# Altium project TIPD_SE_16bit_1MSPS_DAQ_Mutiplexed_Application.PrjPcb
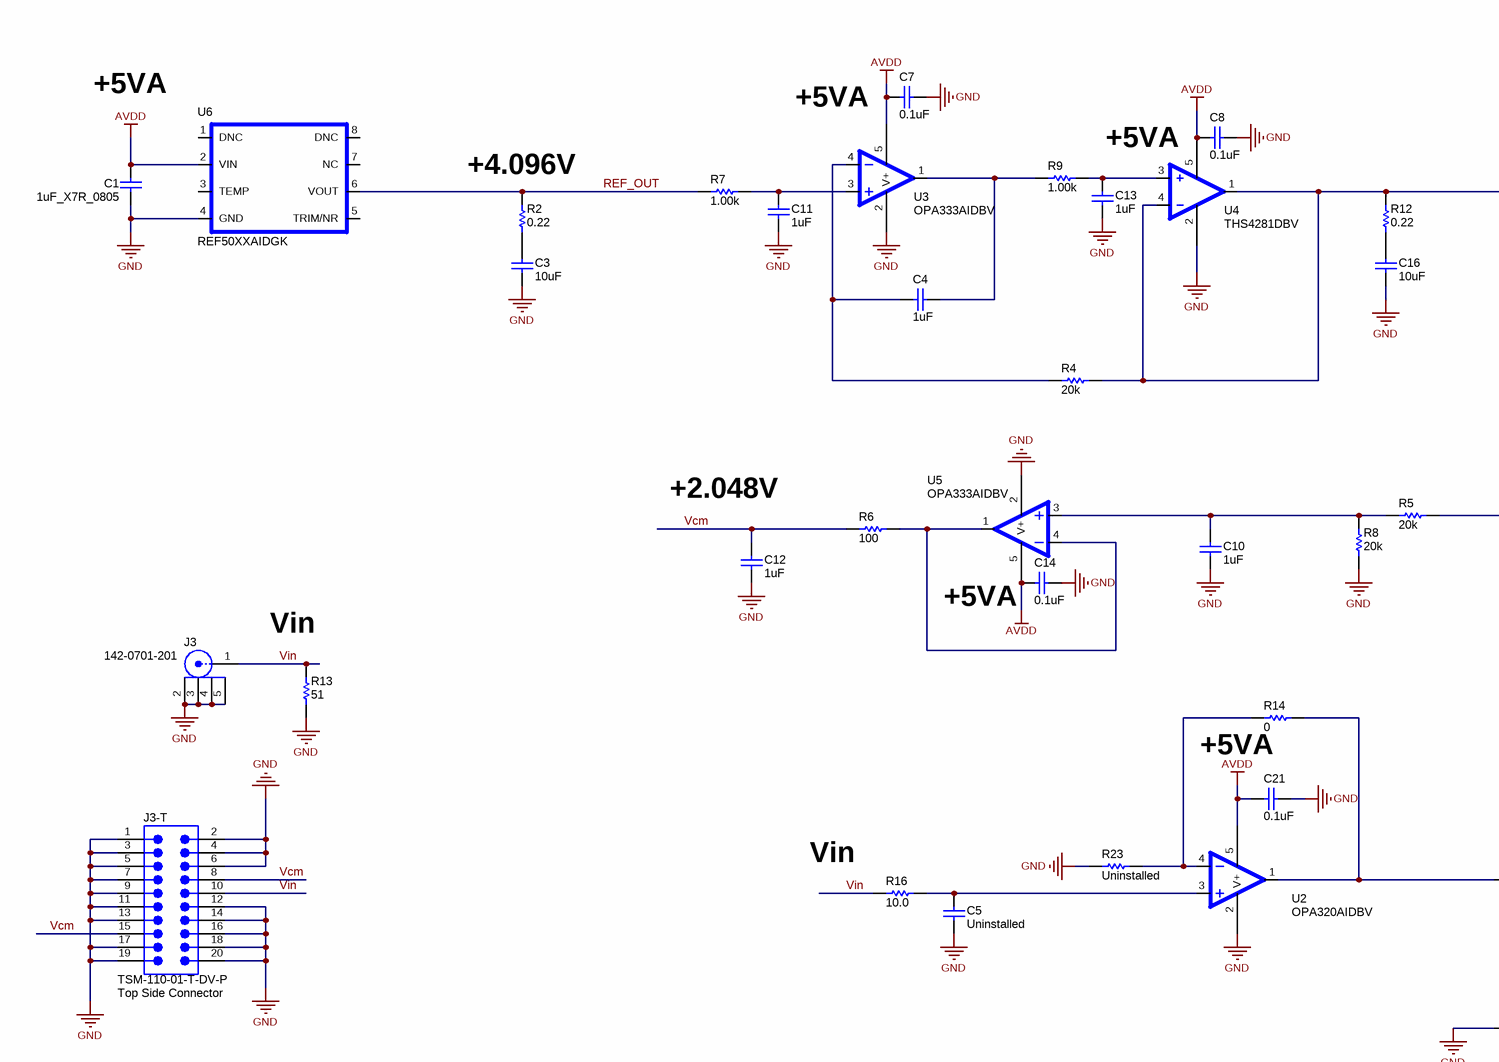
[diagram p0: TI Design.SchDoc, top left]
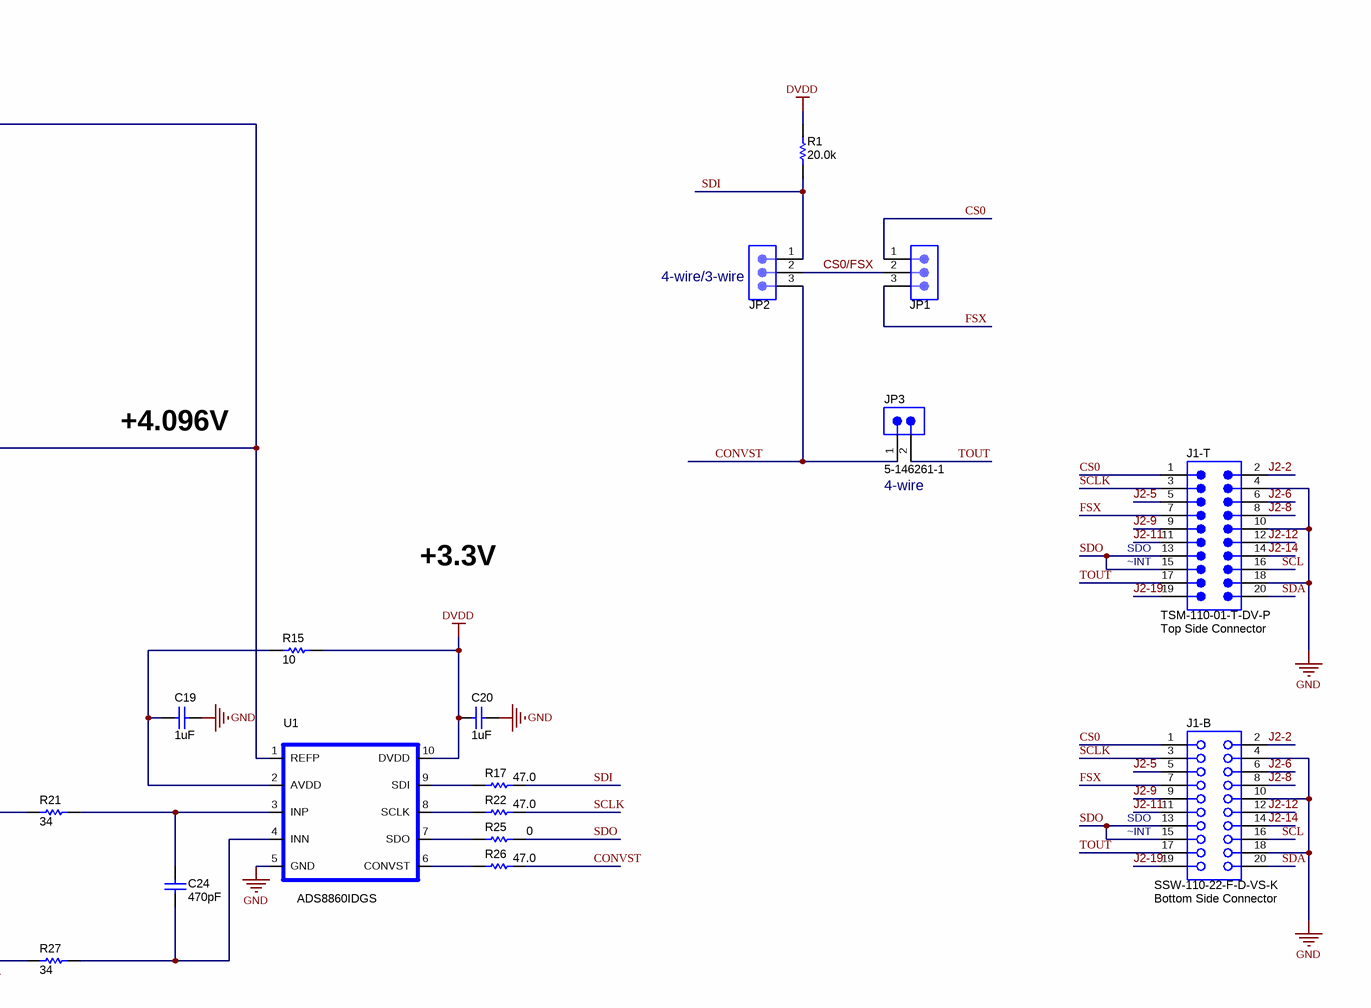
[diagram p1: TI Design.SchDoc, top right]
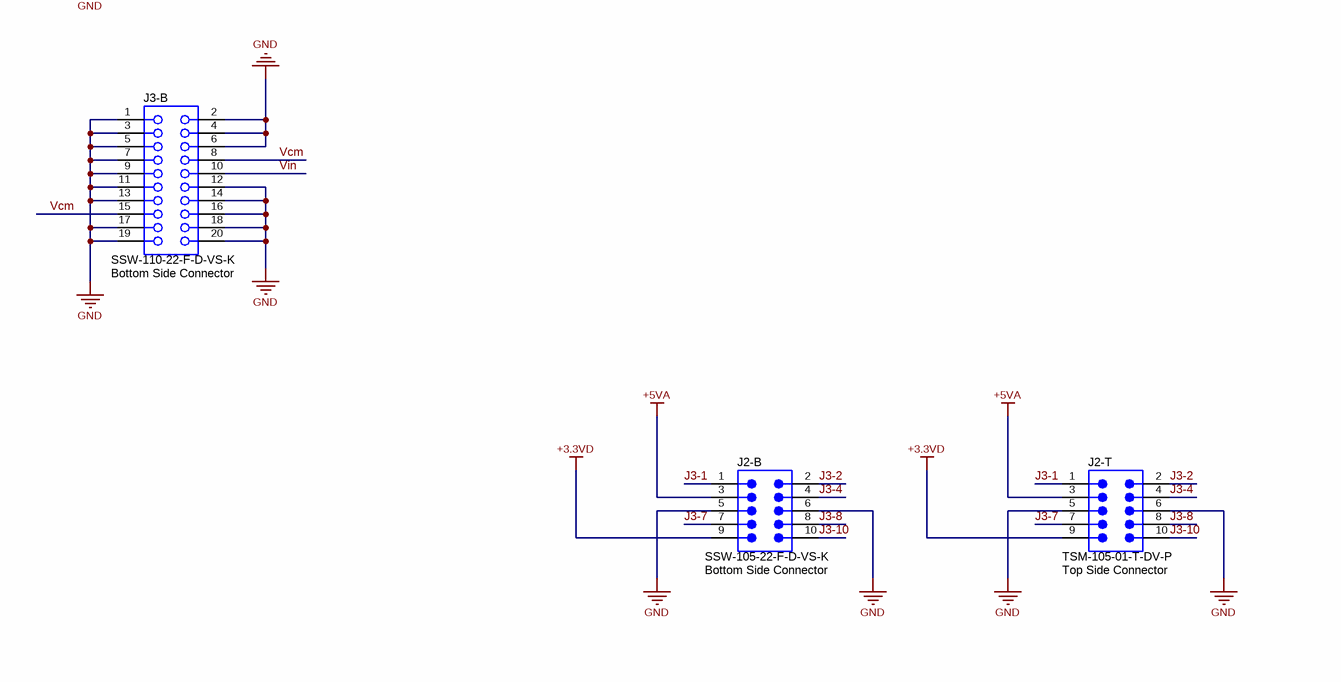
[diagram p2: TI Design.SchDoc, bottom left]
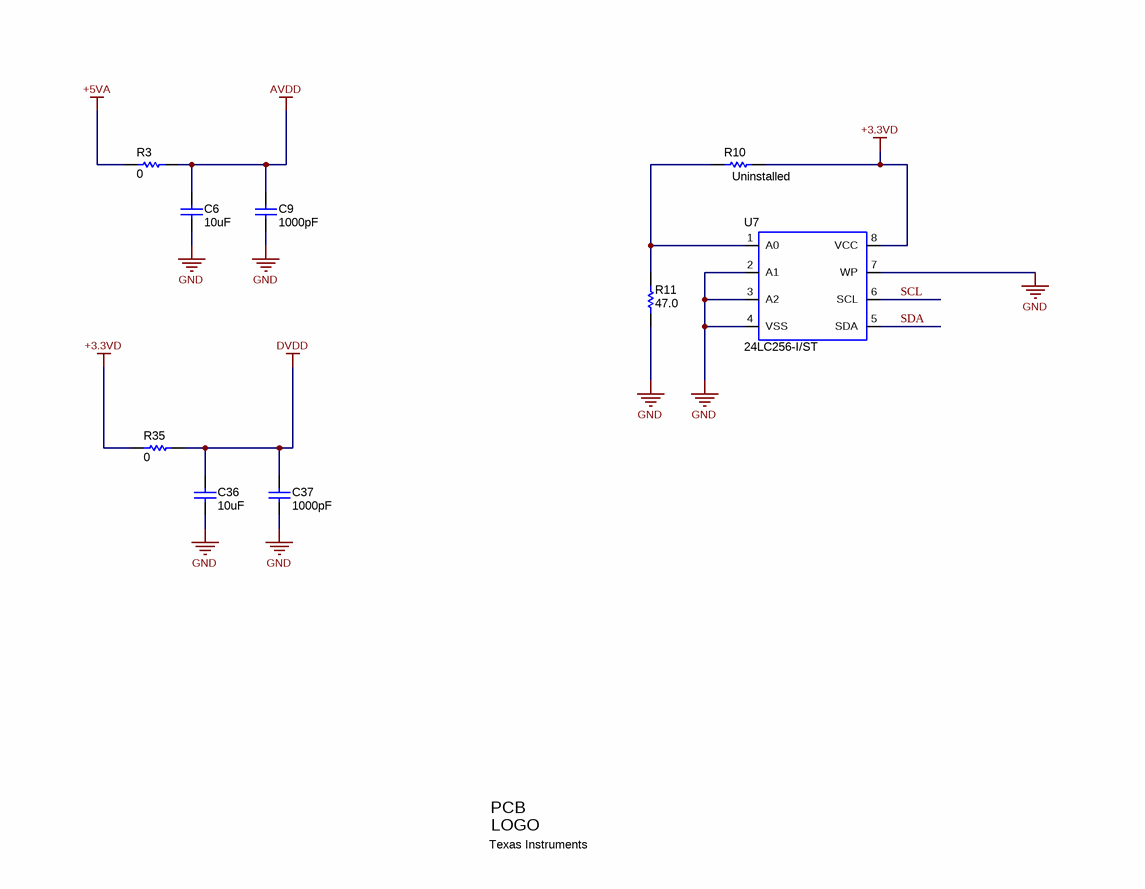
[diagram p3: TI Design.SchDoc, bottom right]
TechSupport: http://www.e2e.ti.com; SCH_Rev: Rev A; PRJ_Title: Schematic for TIDU504; PRJ_Number: TIPD173; PRJ_Engineer: Jason Wu; PRJ_Customer: Precision Converter; PCB_Rev: Rev A; PCB_Layout: Jason Wu; CopyrightYear: 2014
1 sheet, 62 parts. Net scope: global (net labels, ports and power ports of the same name join across sheets).
Board file: TI Design.PcbDoc

## Sheet TI Design.SchDoc: Schematic for TIDU504
size 558 x 431 mm; Date: Not shown in title block; ApprovedBy: Not shown in title block; CheckedBy: Not shown in title block; Author: Not shown in title block; CompanyName: Not shown in title block; Engineer: Not shown in title block; Organization: Not shown in title block; Address1: Not shown in title block; Address2: Not shown in title block; Address3: Not shown in title block; Address4: Not shown in title block; DocumentNumber: 1; Revision: Use project parameter SCH_Rev; SheetNumber: 1; SheetTotal: 1; PageSetup: Record=PageOptions|CenterHorizontal=True|CenterVertical=True|PrintScale=0.62|XCorrection=1.00|YCorrection=1.00|PrintKind=0|BorderSize=5000000|LeftOffset=0|BottomOffset=0|Orientation=2|PaperLength=1000|PaperWidth=1000|Scale=100|PaperSource=15|PrintQuality=600|MediaType=1|DitherType=10|PaperKind=Tabloid (11 x 17")|PrintScaleMode=1

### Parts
C1  ValueDisplayed: 1uF_X7R_0805  [0805_HV]  (hidden comment: C0805C105K8RACTU)
C3  ValueDisplayed: 10uF  [0805_HV]  (hidden comment: GRM21BR70J106KE76L)
C4  ValueDisplayed: 1uF  [0603]  (hidden comment: GRM188R70J105KA01D)
C5  ValueDisplayed: Uninstalled  [0603]  (hidden comment: GRM1885C1E102JA01D)
C6  ValueDisplayed: 10uF  [0805_HV]  (hidden comment: GRM21BR61E106MA73)
C7  ValueDisplayed: 0.1uF  [0603]  (hidden comment: 0603YC104JAT2A)
C8  ValueDisplayed: 0.1uF  [0603]  (hidden comment: 0603YC104JAT2A)
C9  ValueDisplayed: 1000pF  [0603]  (hidden comment: C0603C102J5GAC)
C10  ValueDisplayed: 1uF  [0603]  (hidden comment: GRM188R70J105KA01D)
C11  ValueDisplayed: 1uF  [0603]  (hidden comment: GRM188R70J105KA01D)
C12  ValueDisplayed: 1uF  [0603]  (hidden comment: GRM188R70J105KA01D)
C13  ValueDisplayed: 1uF  [0603]  (hidden comment: GRM188R70J105KA01D)
C14  ValueDisplayed: 0.1uF  [0603]  (hidden comment: 0603YC104JAT2A)
C16  ValueDisplayed: 10uF  [0805_HV]  (hidden comment: GRM21BR71A106KE51L)
C19  ValueDisplayed: 1uF  [0603]  (hidden comment: GRM188R71E105KA12D)
C20  ValueDisplayed: 1uF  [0603]  (hidden comment: GRM188R71E105KA12D)
C21  ValueDisplayed: 0.1uF  [0603]  (hidden comment: 0603YC104JAT2A)
C24  ValueDisplayed: 470pF  [0603]  (hidden comment: GRM1885C1E102JA01D)
C36  ValueDisplayed: 10uF  [0805_HV]  (hidden comment: GRM21BR61E106MA73)
C37  ValueDisplayed: 1000pF  [0603]  (hidden comment: C0603C102J5GAC)
J1-B  Bottom Side Connector  [CONN_SSW-110-22-F-D-VS-K]
J1-T  TSM-110-01-T-DV-P  Comment_1: Top Side Connector  [CONN_TSM-110-01-T-DV-P]
J2-B  SSW-105-22-F-D-VS-K  Comment_1: Bottom Side Connector  [CONN_SSW-105-22-F-D-VS-K]
J2-T  TSM-105-01-T-DV-P  Comment_1: Top Side Connector  [CONN_TSM-105-01-T-DV-P]
J3  142-0701-201  [Johnson_142-0701-20x]
J3-B  Bottom Side Connector  [CONN_SSW-110-22-F-D-VS-K]
J3-T  TSM-110-01-T-DV-P  Comment_1: Top Side Connector  [CONN_TSM-110-01-T-DV-P]
JP1  PBC03SAAN  [PBC03SAAN]  (value not drawn)
JP2  PBC03SAAN  [PBC03SAAN]  (value not drawn)
JP3  5-146261-1  [CONN_5-146261-1]
Logo1  Texas Instruments  [TI_Stacked_SolderMask_Medium]  (no BOM)
R1  value 20.0k  [0603]  (hidden comment: CRCW060320K0FKEA)
R2  value 0.22  [0603]  (hidden comment: CRCW060320K0FKEA)
R3  value 0  [0603]  (hidden comment: ERJ-3GEY0R00V)
R4  value 20k  [0603]  (hidden comment: CRCW060320K0FKEA)
R5  value 20k  [0603]  (hidden comment: RG1608P-102-B-T5)
R6  value 100  [0603]  (hidden comment: RG1608P-102-B-T5)
R7  value 1.00k  [0603]  (hidden comment: RG1608P-102-B-T5)
R8  value 20k  [0603]  (hidden comment: RG1608P-102-B-T5)
R9  value 1.00k  [0603]  (hidden comment: RG1608P-102-B-T5)
R10  Uninstalled  [0603]
R11  value 47.0  [0603]  (hidden comment: RC0603FR-0747RL)
R12  value 0.22  [0603]  (hidden comment: ERJ-3RQFR22V)
R13  value 51  [0805_HV]  (hidden comment: RG2012P-510-B-T5)
R14  value 0  [0603]  (hidden comment: RC0603FR-0710RL)
R15  value 10  [0603]  (hidden comment: RC0603FR-0710RL)
R16  value 10.0  [0603]  (hidden comment: RC0603FR-0710RL)
R17  value 47.0  [0603]  (hidden comment: RC0603FR-0710RL)
R21  value 34  [0603]  (hidden comment: RC0603FR-0710RL)
R22  value 47.0  [0603]  (hidden comment: RC0603FR-0710RL)
R23  value Uninstalled  [0603]  (hidden comment: RC0603FR-0710RL)
R25  value 0  [0603]  (hidden comment: RC0603FR-0710RL)
R26  value 47.0  [0603]  (hidden comment: RC0603FR-0710RL)
R27  value 34  [0603]  (hidden comment: RC0603FR-0710RL)
R35  value 0  [0603]  (hidden comment: ERJ-3GEY0R00V)
U1  ADS8860IDGS  [DGS_10P2]
U2  OPA320AIDBV  [SOT23-5P]
U3  OPA333AIDBV  [SOT23-5P]
U4  THS4281DBV  [DBV-5]
U5  OPA333AIDBV  [SOT23-5P]
U6  REF50XXAIDGK  [DGK8]
U7  24LC256-I/ST  [TSSOP-8]

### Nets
+3.3VD: J2-B.9 J2-T.9 R10.2 R35.1 U7.8(VCC)
+5VA: J2-B.3 J2-T.3 R3.1
AVDD: C1.1 C6.1 C7.1 C8.1 C9.2 C14.1 C21.1 R3.2 U2.5(V+) U3.5(V+) U4.5(VDD) U5.5(V+) U6.2(VIN)
DVDD: C20.2 C36.1 C37.2 R1.1 R15.2 R35.2 U1.10(DVDD)
GND: C1.2 C3.2 C5.2 C6.2 C7.2 C8.2 C9.1 C10.1 C11.1 C12.1 C13.1 C14.2 C16.1 C19.1 C20.1 C21.2 C36.2 C37.1 J1-B.4 J1-B.10 J1-B.18 J1-T.4 J1-T.10 J1-T.18 J2-B.5 J2-B.6 J2-T.5 J2-T.6 J3.2 J3.3 J3.4 J3.5 J3-B.1 J3-B.2 J3-B.3 J3-B.4 J3-B.5 J3-B.6 J3-B.7 J3-B.9 J3-B.11 J3-B.12 J3-B.13 J3-B.14 J3-B.16 J3-B.17 J3-B.18 J3-B.19 J3-B.20 J3-T.1 J3-T.2 J3-T.3 J3-T.4 J3-T.5 J3-T.6 J3-T.7 J3-T.9 J3-T.11 J3-T.12 J3-T.13 J3-T.14 J3-T.16 J3-T.17 J3-T.18 J3-T.19 J3-T.20 R8.1 R11.2 R13.1 R23.1 R27.1 U1.5(GND) U2.2(V-) U3.2(V-) U4.2(GND) U5.2(V-) U6.4(GND) U7.2(A1) U7.3(A2) U7.4(VSS) U7.7(WP)
CONVST: JP2.3 JP3.1 R26.2
CS0: J1-B.1 J1-T.1 JP1.1
CS0/FSX: JP1.2 JP2.2
FSX: J1-B.7 J1-T.7 JP1.3
J2-2: J1-B.2 J1-T.2
J2-5: J1-B.5 J1-T.5
J2-6: J1-B.6 J1-T.6
J2-8: J1-B.8 J1-T.8
J2-9: J1-B.9 J1-T.9
J2-11: J1-B.11 J1-T.11
J2-12: J1-B.12 J1-T.12
J2-14: J1-B.14 J1-T.14
J2-19: J1-B.19 J1-T.19
J3-1: J2-B.1 J2-T.1
J3-2: J2-B.2 J2-T.2
J3-4: J2-B.4 J2-T.4
J3-7: J2-B.7 J2-T.7
J3-8: J2-B.8 J2-T.8
J3-10: J2-B.10 J2-T.10
REF_OUT: R2.1 R7.1 U6.6(VOUT)
SCL: J1-B.16 J1-T.16 U7.6(SCL)
SCLK: J1-B.3 J1-T.3 R22.2
SDA: J1-B.20 J1-T.20 U7.5(SDA)
SDI: JP2.1 R1.2 R17.2
SDO: J1-B.13 J1-B.15 J1-T.13 J1-T.15 R25.2
TOUT: J1-B.17 J1-T.17 JP3.2
Vcm: C12.2 J3-B.8 J3-B.15 J3-T.8 J3-T.15 R6.1
Vin: J3.1 J3-B.10 J3-T.10 R13.2 R16.1
NetC3_1: C3.1 R2.2
NetC4_1: C4.1 R9.1 U3.1(OUT)
NetC4_2: C4.2 R4.2 U3.4
NetC5_1: C5.1 R16.2 U2.3
NetC10_2: C10.2 R5.1 R8.2 U5.3
NetC11_2: C11.2 R7.2 U3.3
NetC13_2: C13.2 R9.2 U4.3
NetC16_2: C16.2 R12.1
NetC19_2: C19.2 R15.1 U1.2(AVDD)
NetC24_1: C24.1 R21.2 U1.3(INP)
NetC24_2: C24.2 R27.2 U1.4(INN)
NetR4_1: R4.1 R5.2 R12.2 U1.1(REFP) U4.1(OUT) U4.4
NetR6_2: R6.2 U5.1(OUT) U5.4
NetR10_1: R10.1 R11.1 U7.1(A0)
NetR14_1: R14.1 R23.2 U2.4
NetR14_2: R14.2 R21.1 U2.1(OUT)
NetR17_1: R17.1 U1.9(SDI)
NetR22_1: R22.1 U1.8(SCLK)
NetR25_1: R25.1 U1.7(SDO)
NetR26_1: R26.1 U1.6(CONVST)

Not connected (* = marked no-connect by the designer): U6 1(DNC) 3(TEMP) 5(TRIM/NR) 7(NC) 8(DNC)

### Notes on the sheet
- +5VA
- (near R2) +4.096V
- (near JP2) 4-wire/3-wire
- (near C12) +2.048V
- +4.096V
- (near JP3) 4-wire
- Vin
- +3.3V
- (near J1-T) SDO
- (near J1-T) ~INT
- (near R14) +5VA
- (near R16) Vin
- (near J1-B) SDO
- (near J1-B) ~INT

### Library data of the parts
C1 = C0805C105K8RACTU: CAP, CERM, 1uF, 10V, +/-10%, X7R, 0805; Manufacturer: Kemet; Polarized: N; CompType: Capacitor; U/M: EA; Cap_F: 0.000001; Tolerance_%: 10; ESR_Ohm: 0.015; Value1: 0.015 ohm; IRMS_A: 8.19; TaMin_C: -55; TaMax_C: 125; Cap_Case: 0805
C3 = GRM21BR70J106KE76L: CAP, CERM, 10uF, 6.3V, +/-10%, X7R, 0805; Manufacturer: MuRata; Polarized: N; CompType: Capacitor; U/M: EA; Cap_F: 0.00001; Tolerance_%: 10; Value1: Unknown; VDC_V: 6.3; TaMin_C: -55; TaMax_C: 125; Cap_Case: 0805
C4 C10-C13 = GRM188R70J105KA01D: CAP, CERM, 1uF, 6.3V, +/-10%, X7R, 0603; Manufacturer: MuRata; Polarized: N; CompType: Capacitor; U/M: EA; Cap_F: 0.000001; Tolerance_%: 10; VDC_V: 6.3; TaMin_C: -55; TaMax_C: 125
C5 C24 = GRM1885C1E102JA01D: CAP, CERM, 1000pF, 25V, +/-5%, C0G/NP0, 0603; Manufacturer: MuRata; Polarized: N; CompType: Capacitor; U/M: EA; Cap_F: 0.000000001; Tolerance_%: 5; Value1: Unknown; VDC_V: 25; TaMin_C: -55; TaMax_C: 125
C6 C36 = GRM21BR61E106MA73: CAP, CERM, 10uF, 25V, +/-20%, X5R, 0805; Manufacturer: MuRata; Polarized: N; CompType: Capacitor; U/M: EA; Cap_F: 0.00001; Tolerance_%: 20; Value1: Unknown; VDC_V: 25; TaMin_C: -55; TaMax_C: 85; Cap_Case: 0805
C7 C8 C14 C21 = 0603YC104JAT2A: CAP, CERM, 0.1uF, 16V, +/-5%, X7R, 0603; Manufacturer: AVX; Polarized: N; CompType: Capacitor; U/M: EA; Cap_F: 0.0000001; Tolerance_%: 5; ESR_Ohm: 0.039; Value1: 0.039 ohm; VDC_V: 16; TaMin_C: -55; TaMax_C: 125
C9 C37 = C0603C102J5GAC: CAP, CERM, 1000pF, 50V, +/-5%, C0G/NP0, 0603; Manufacturer: Kemet; Polarized: N; CompType: Capacitor; U/M: EA; Cap_F: 0.000000001; Tolerance_%: 5; Value1: Unknown; VDC_V: 50; TaMin_C: -55; TaMax_C: 125
C16 = GRM21BR71A106KE51L: CAP, CERM, 10uF, 10V, +/-10%, X7R, 0805; Manufacturer: MuRata; Polarized: N; CompType: Capacitor; U/M: EA; Cap_F: 0.00001; Tolerance_%: 10; ESR_Ohm: 0.003; Value1: 0.003 ohm; TaMin_C: -55; TaMax_C: 125; Cap_Case: 0805
C19 C20 = GRM188R71E105KA12D: CAP, CERM, 1uF, 25V, +/-10%, X7R, 0603; Manufacturer: MuRata; Polarized: N; CompType: Capacitor; U/M: EA; Cap_F: 0.000001; Tolerance_%: 10; Value1: Unknown; VDC_V: 25; TaMin_C: -55; TaMax_C: 125
J1-B J3-B = SSW-110-22-F-D-VS-K: Connector, Receptacle, 100mil, 10x2, Gold plated, SMD; Manufacturer: Samtec, Inc.; SymbolCreator: a0412235; U/M: EA
J1-T J3-T = TSM-110-01-T-DV-P: Header, 100mil, 10x2, SMD; Manufacturer: Samtec, Inc.; SymbolCreator: a0412235; CompType: Connector; U/M: EA
J2-B = SSW-105-22-F-D-VS-K: Connector, Header, 10-Pos (10x2), Receptacle, 100x100-mil Pitch; Manufacturer: Samtec, Inc.; SymbolCreator: a0412235; U/M: EA
J2-T = TSM-105-01-T-DV-P: Header, 100mil, 5x2, SMD; Manufacturer: Samtec, Inc.; SymbolCreator: a0412235; CompType: Connector; U/M: EA
J3 = 142-0701-201: Connector, TH, SMA; Manufacturer: Emerson Network Power; SymbolCreator: X0208326; U/M: EA
JP1 JP2 = PBC03SAAN: Header, TH, 100mil, 1x3, Gold plated, 230 mil above insulator; Manufacturer: Sullins Connector Solutions; U/M: EA
JP3 = 5-146261-1: Header, 100mil, 2x1, Gold plated, TH; Manufacturer: TE Connectivity; SymbolCreator: a0412235; U/M: EA
Logo1 = TI_Logo: Texas Instrument Corporate Signature; SymbolCreator: a0412235
R1 = CRCW060320K0FKEA: RES, 20.0k ohm, 1%, 0.1W, 0603; Manufacturer: Vishay-Dale; CompType: Resistor; Res_ohm: 20000; Value_Code: 20k0; Tolerance_%: 1; Power_W: 0.1; VDC_V: 75; TempCo: 100 ppm/C; EIA_Code: E96; U/M: EA
R2 R4 = CRCW060320K0FKEA: RES, 20.0k ohm, 1%, 0.1W, 0603; Manufacturer: Vishay-Dale; Alternate Manufacturer: Any; Alternate PartNumber: Equivalent; CompType: Resistor; Res_ohm: 20000; Value_Code: 20k0; Tolerance_%: 1; Power_W: 0.1; VDC_V: 75; TempCo: 100 ppm/C; EIA_Code: E96; U/M: EA
R3 R35 = ERJ-3GEY0R00V: RES, 0 ohm, 5%, 0.1W, 0603; Manufacturer: Panasonic; CompType: Resistor; Value_Code: 0000; Tolerance_%: 5; Power_W: 0.1; VDC_V: 50; TempCo: 600 ppm/C; EIA_Code: E24; U/M: EA
R5-R9 = RG1608P-102-B-T5: RES, 1.00k ohm, 0.1%, 0.1W, 0603; Manufacturer: Susumu Co Ltd; CompType: Resistor; Res_ohm: 1000; Value_Code: 1k00; Tolerance_%: 0.1; VDC_V: 75; TempCo: 25 ppm/C; EIA_Code: E192; U/M: EA
R10 = ERJ-3GEY0R00V: CompType: Resistor; Res_ohm: 0; Value_Code: 0000; Tolerance_%: 5; Value1: 5%; Power_W: 0.1; Value2: 0.1W; VDC_V: 50; TempCo: 600 ppm/C; EIA_Code: E24; U/M: EA
R11 = RC0603FR-0747RL: RES, 47.0 ohm, 1%, 0.1W, 0603; Manufacturer: Yageo America; CompType: Resistor; Res_ohm: 47; Value_Code: 47R0; Tolerance_%: 1; Power_W: 0.1; VDC_V: 150; TempCo: 200 ppm/C; U/M: EA
R12 = ERJ-3RQFR22V: RES, 0.22 ohm, 1%, 0.1W, 0603; Manufacturer: Panasonic; Alternate Manufacturer: Any; Alternate PartNumber: Equivalent; CompType: Resistor; Value_Code: R220; Tolerance_%: 1; Power_W: 0.1; TempCo: 300 ppm/C; EIA_Code: E96; U/M: EA
R13 = RG2012P-510-B-T5: RES, 51 ohm, 0.1%, 0.125W, 0805; Manufacturer: Susumu Co Ltd; CompType: Resistor; Value_Code: 51R0; Tolerance_%: 0.1; Power_W: 0.125; VDC_V: 100; TempCo: 25 ppm/C; U/M: EA
R14 R16 R17 R21-R23 R25-R27 = RC0603FR-0710RL: RES, 10.0 ohm, 1%, 0.1W, 0603; Manufacturer: Yageo America; CompType: Resistor; Res_ohm: 10; Value_Code: 10R0; Tolerance_%: 1; Power_W: 0.1; VDC_V: 150; TempCo: 200 ppm/C; EIA_Code: E96; U/M: EA
R15 = RC0603FR-0710RL: RES, 10.0 ohm, 1%, 0.1W, 0603; Manufacturer: Yageo America; CompType: Resistor; Value_Code: 10R0; Tolerance_%: 1; Power_W: 0.1; VDC_V: 150; TempCo: 200 ppm/C; EIA_Code: E96; U/M: EA
U1 = ADS886XIDGS: IC, 16 Bit 1 MSPS, Serial Interface; Manufacturer: TI; Alternate Manufacturer: None; Area: 44100
U2 U3 U5 = OPA333AIDBV: IC, 1.8V, microPower, CMOS Op Amp, Zer?Drift Series; Manufacturer: TI; Alternate Manufacturer: None; Area: 31500
U4 = THS4281DBV: IC, Very Low-Power, High-Speed, R-R In/Output Op-Amp; Manufacturer: TI; Alternate Manufacturer: None; Area: 28800
U6 = REF50XXAIDGK: IC, Precision Voltage Reference, xxV,; Manufacturer: TI; Alternate Manufacturer: None; Area: 75900
U7 = 24LC256-I/ST: Manufacturer: Microchip; SymbolCreator: a0872359; CompType: EEPROM; U/M: EA

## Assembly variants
001: all parts fitted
